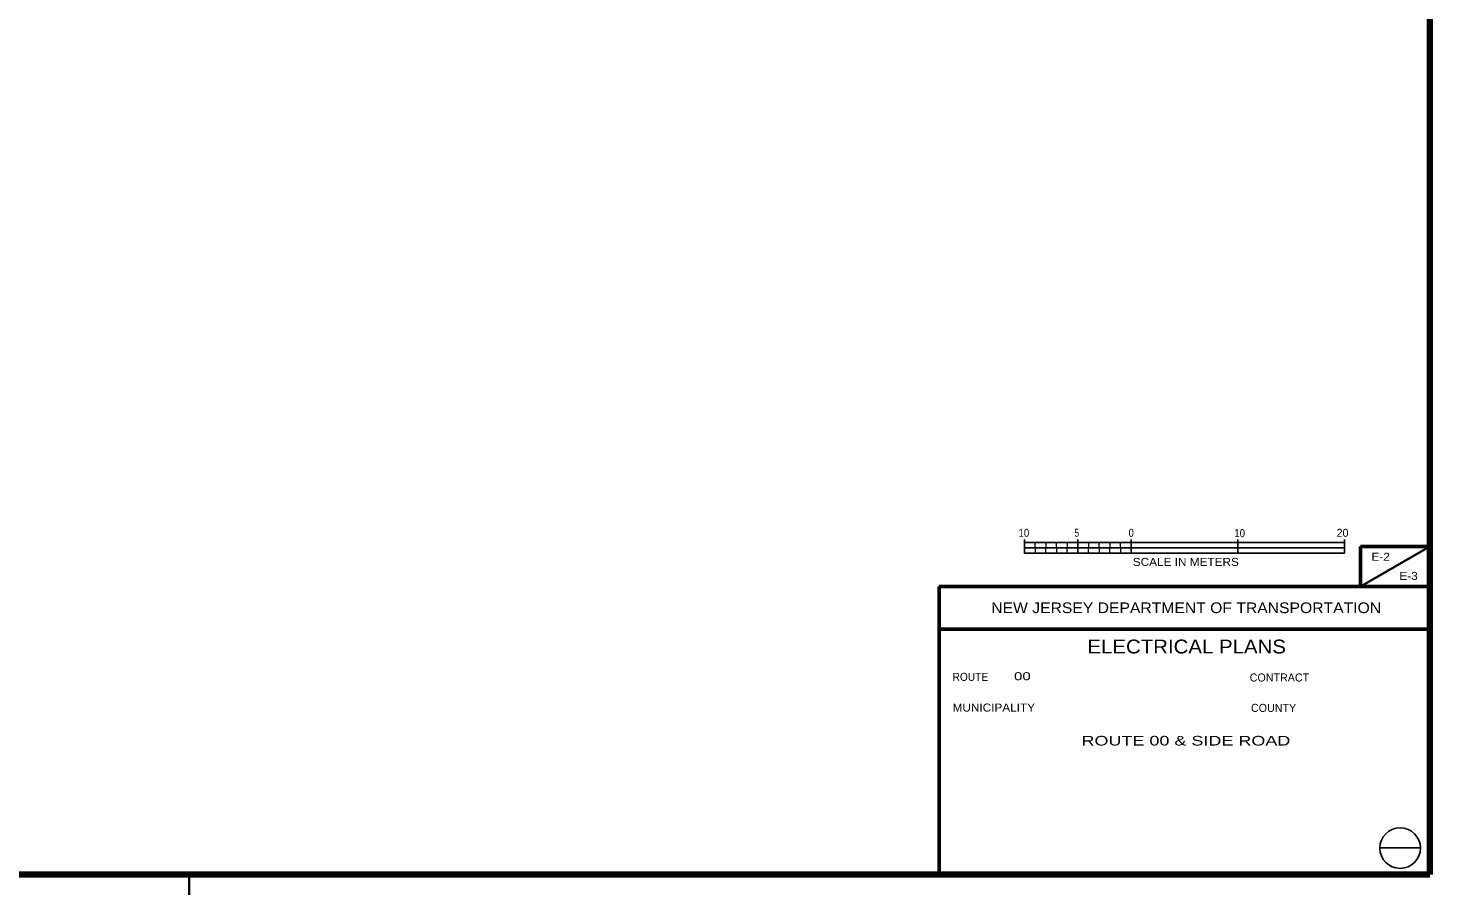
# Model space of a CAD drawing. Extents: x 168203 to 169864, y 223196 to 223870.
# Drawn here: x 169229.9 to 169361.3, y 223366.7 to 223448 of the extents above; entities that cross this region are included whole.
import ezdxf
from ezdxf.enums import TextEntityAlignment as Align

# ---------------------------------------------------------------- set-up
doc = ezdxf.new("R2010")
doc.units = 0
doc.header["$LTSCALE"] = 0.3
doc.layers.add('1', color=7, linetype='Continuous', lineweight=13)
doc.layers.add('25', color=7, linetype='Continuous', lineweight=35)

msp = doc.modelspace()

# ---------------------------------------------------------------- linework, layer by layer
at = {"layer": '1', "lineweight": 25}
for p, q in [((169323.2833, 223399.7226), (169353.2833, 223399.7226)), ((169325.1233, 223399.7226), (169326.1433, 223399.7226)), ((169327.1633, 223399.7226), (169328.1833, 223399.7226)), ((169328.2833, 223400.0201), (169328.2833, 223398.7226)), ((169329.2033, 223399.7226), (169330.2233, 223399.7226)), ((169331.2433, 223399.7226), (169332.2633, 223399.7226)), ((169333.2833, 223400.0201), (169333.2833, 223398.7226)), ((169343.2833, 223400.0201), (169343.2833, 223398.7226)), ((169353.2833, 223400.0201), (169353.2833, 223398.7226)), ((169323.2833, 223399.2226), (169353.2833, 223399.2226))]:
    msp.add_line(p, q, dxfattribs=at)
at = {"layer": '1', "lineweight": 35}
msp.add_line((169245.0333, 223368.6089), (169245.0333, 223366.6889), dxfattribs=at)
at = {"layer": '1', "lineweight": 158}
msp.add_lwpolyline([(169361.2833, 223368.6089), (169361.2833, 223530.6089), (169128.7833, 223530.6089), (169128.7833, 223368.6089)], close=True, dxfattribs=at)
at = {"layer": '1', "lineweight": 25}
msp.add_lwpolyline([(169323.2833, 223400.0201), (169323.2833, 223398.7226), (169353.2833, 223398.7226)], dxfattribs=at)
at = {"layer": '1'}
for points in [[(169323.2833, 223399.2226), (169324.2833, 223399.2226), (169324.2833, 223399.7226), (169323.2833, 223399.7226)], [(169325.2833, 223399.2226), (169326.2833, 223399.2226), (169326.2833, 223399.7226), (169325.2833, 223399.7226)], [(169327.2833, 223399.2226), (169328.2833, 223399.2226), (169328.2833, 223399.7226), (169327.2833, 223399.7226)], [(169329.2833, 223399.2226), (169330.2833, 223399.2226), (169330.2833, 223399.7226), (169329.2833, 223399.7226)], [(169331.2833, 223399.2226), (169332.2833, 223399.2226), (169332.2833, 223399.7226), (169331.2833, 223399.7226)], [(169333.2833, 223399.2226), (169343.2833, 223399.2226), (169343.2833, 223399.7226), (169333.2833, 223399.7226)], [(169324.2833, 223398.7226), (169325.2833, 223398.7226), (169325.2833, 223399.2226), (169324.2833, 223399.2226)], [(169326.2833, 223398.7226), (169327.2833, 223398.7226), (169327.2833, 223399.2226), (169326.2833, 223399.2226)], [(169328.2833, 223398.7226), (169329.2833, 223398.7226), (169329.2833, 223399.2226), (169328.2833, 223399.2226)], [(169330.2833, 223398.7226), (169331.2833, 223398.7226), (169331.2833, 223399.2226), (169330.2833, 223399.2226)], [(169332.2833, 223398.7226), (169333.2833, 223398.7226), (169333.2833, 223399.2226), (169332.2833, 223399.2226)], [(169343.2833, 223398.7226), (169353.2833, 223398.7226), (169353.2833, 223399.2226), (169343.2833, 223399.2226)]]:
    msp.add_lwpolyline(points, close=True, dxfattribs=at)
at = {"layer": '25'}
msp.add_line((169354.7833, 223395.6089), (169361.2833, 223399.3589), dxfattribs=at)
at = {"layer": '25', "lineweight": 53}
for p, q in [((169354.7833, 223399.3589), (169361.2833, 223399.3589)), ((169354.7833, 223399.3589), (169354.7833, 223395.6089)), ((169315.2833, 223368.6089), (169315.2833, 223395.6089)), ((169361.2833, 223395.6089), (169315.2833, 223395.6089)), ((169315.2833, 223391.6089), (169361.2833, 223391.6089))]:
    msp.add_line(p, q, dxfattribs=at)
at = {"layer": '25', "lineweight": 25}
msp.add_line((169356.5733, 223371.0989), (169360.3833, 223371.0989), dxfattribs=at)
msp.add_circle((169358.4841, 223371.0851), 1.9049, dxfattribs=at)

# ---------------------------------------------------------------- texts
at = {"layer": '1'}
for s, width, p in [('10', 0.9, (169323.2342, 223400.2626)), ('5', 0.75, (169328.1859, 223400.2626)), ('0', 0.85, (169333.2884, 223400.2626)), ('10', 0.9, (169343.4542, 223400.2326)), ('SCALE IN METERS', 1.1, (169338.4047, 223397.5326))]:
    msp.add_text(s, height=0.7501, dxfattribs=dict(at, width=width)).set_placement(p, align=Align.CENTER)
msp.add_text('20', height=0.7501, dxfattribs=at).set_placement((169353.095, 223400.2626), align=Align.CENTER)
at = {"layer": '25'}
for s, height, width, p in [('E-2', 0.75, 1.1, (169356.6606, 223398.0129)), ('E-3', 0.75, 1.1, (169359.2798, 223396.2235)), ('NEW JERSEY DEPARTMENT OF TRANSPORTATION', 1, 1.1, (169338.4408, 223393.1089)), ('ELECTRICAL PLANS', 1.3, 1.1, (169338.488, 223389.3256)), ('             ROUTE 00 & SIDE ROAD            ', 0.9, 1.4, (169338.181, 223380.6989))]:
    msp.add_text(s, height=height, dxfattribs=dict(at, width=width)).set_placement(p, align=Align.CENTER)
for s, width, p in [('ROUTE', 0.95, (169316.5533, 223386.7589)), ('00                        ', 1.4, (169322.3133, 223386.8189)), ('MUNICIPALITY', 1.1, (169316.5533, 223383.8789))]:
    msp.add_text(s, height=0.75, dxfattribs=dict(at, width=width)).set_placement(p)
for s, p in [('CONTRACT', (169344.3933, 223386.6989)), ('COUNTY', (169344.5133, 223383.8489))]:
    msp.add_text(s, height=0.75, dxfattribs=at).set_placement(p)

doc.saveas('drawing.dxf')
